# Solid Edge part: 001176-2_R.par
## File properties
Last saved by: morva
Revision: 82
Accuracy: 0.990
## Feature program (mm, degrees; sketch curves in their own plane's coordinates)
body "unnamed Body 1"
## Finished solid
Body 1: solid body, 78 faces, 236 edges, 166 vertices.
  Faces by surface: cylinder 34, plane 19, spline 13, torus 6, spun 4, sphere 1, swept 1
  Edges by curve: curve on surface 170, line 53, spline 11, circle 2
Bounding box of the edges (mm; curved faces can reach further): 52.643 x 56.787 x 104.341, from (388.4284, 338.6813, 165.1679) to (441.0712, 395.4681, 269.5092).
Cylindrical faces by radius (mm): R0.75 x2, R1 x2, R1.5 x2, R2 x5, R2.5 x2, R3.5 x4, R4.1256 x1, R4.4184 x1, R5.5 x4, R7.5 x1, R9 x1, R10 x2, R12 x1, R15.2628 x1, R41.0833 x2, R158.12 x2, R1237.1852 x1
Toroidal faces (ring radius, tube radius in mm): R10.9892 r1.0001 x2, R157.2371 r1 x2, R1236.1852 r1 x2
Spherical faces by radius (mm): R1.0025 x1
Planar faces by outward normal: oblique 19
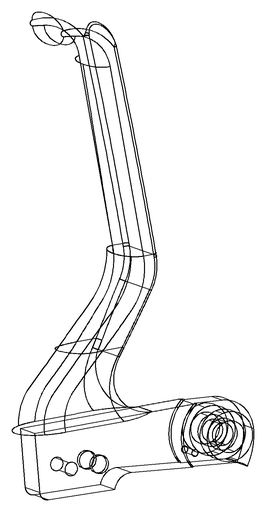
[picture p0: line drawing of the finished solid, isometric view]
